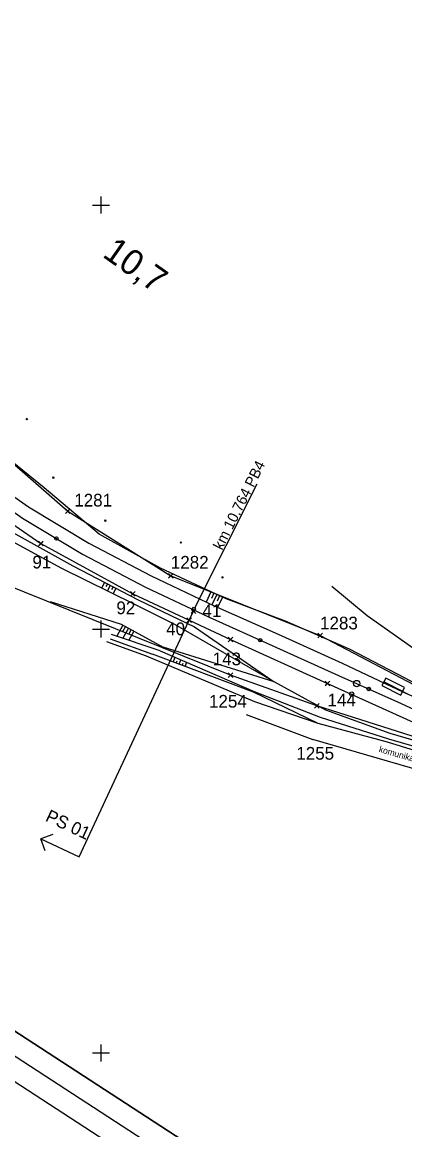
# Model space of a CAD drawing. Extents: x -866402 to -860377, y -1041908 to -1038598.
# Drawn here: x -861718.6 to -861628.2, y -1039718.2 to -1039456.8 of the extents above; entities that cross this region are included whole.
import ezdxf

# ---------------------------------------------------------------- set-up
doc = ezdxf.new("R2010")
doc.units = 0
for name, color, linetype in [('PS 01 prvky', 7, 'Continuous'), ('PS 01 trasa', 7, 'Continuous'), ('PS 02 trasa', 7, 'Continuous'), ('SZDC', 7, 'Continuous'), ('Vrstva 1', 7, 'Continuous'), ('Vrstva 17', 7, 'Continuous'), ('Vrstva 48', 7, 'Continuous'), ('Vrstva 49', 7, 'Continuous'), ('Vrstva 5', 7, 'Continuous'), ('Vrstva 51', 7, 'Continuous'), ('Vrstva 60', 7, 'Continuous'), ('Vrstva 7', 7, 'Continuous')]:
    doc.layers.add(name, color=color, linetype=linetype)

msp = doc.modelspace()

# ---------------------------------------------------------------- linework, layer by layer
at = {"layer": 'PS 01 prvky'}
for p, q in [((-861677.82, -1039594.99), (-861663.08, -1039565.75)), ((-861632.76, -1039611.58), (-861633.66, -1039613.36)), ((-861628.29, -1039613.81), (-861632.76, -1039611.58)), ((-861633.66, -1039613.36), (-861629.18, -1039615.6)), ((-861629.18, -1039615.6), (-861628.29, -1039613.81)), ((-861628.74, -1039614.71), (-861626.95, -1039615.6))]:
    msp.add_line(p, q, dxfattribs=at)
msp.add_lwpolyline([(-861677.61, -1039595.2), (-861678.29, -1039594.89), (-861678.6, -1039595.57), (-861677.92, -1039595.88)], close=True, dxfattribs=at)
for points in [[(-861678.11, -1039595.38), (-861678.45, -1039595.23)], [(-861628.74, -1039614.71), (-861633.21, -1039612.47)]]:
    msp.add_lwpolyline(points, dxfattribs=at)
at = {"layer": 'PS 01 trasa'}
for p, q in [((-861705.13, -1039653.71), (-861679.17, -1039597.93)), ((-861711.38, -1039648.46), (-861714.19, -1039649.49)), ((-861714.19, -1039649.49), (-861705.13, -1039653.71)), ((-861713.17, -1039652.31), (-861714.19, -1039649.49))]:
    msp.add_line(p, q, dxfattribs=at)
for points in [[(-861734.94, -1039565.48), (-861714.17, -1039579.85), (-861692.5, -1039591.72), (-861679.17, -1039597.93)], [(-861679.17, -1039597.93), (-861678.17, -1039595.76)]]:
    msp.add_lwpolyline(points, dxfattribs=at)
at = {"layer": 'PS 02 trasa'}
msp.add_lwpolyline([(-861734.94, -1039565.48), (-861714.17, -1039579.85), (-861692.5, -1039591.72), (-861679.17, -1039597.93), (-861669.42, -1039602.48), (-861646.49, -1039612.82), (-861623.81, -1039623.04), (-861599.73, -1039634.4), (-861591.94, -1039638.84), (-861559.23, -1039660.24), (-861540.24, -1039675.31), (-861522.22, -1039692.58), (-861505.35, -1039711.25), (-861489.08, -1039730.28), (-861472.81, -1039749.33), (-861456.55, -1039768.41), (-861440.35, -1039787.41)], dxfattribs=at)
at = {"layer": 'SZDC'}
for points in [[(-861729.85, -1039553), (-861707.85, -1039572.19), (-861683.49, -1039587.43), (-861648.26, -1039601.57), (-861584.91, -1039634.69), (-861543.49, -1039657.42), (-861534.95, -1039665.88), (-861527.09, -1039673.66), (-861519.15, -1039681.53), (-861498.94, -1039705.92), (-861489.43, -1039717.4), (-861392.94, -1039828.48), (-861296.45, -1039939.55), (-861273.55, -1039965.91), (-861261.75, -1039976.4), (-861207.66, -1040016.44)], [(-861236.71, -1040010.09), (-861295.08, -1039961.46), (-861327.14, -1039923.72), (-861355.62, -1039890.18), (-861362.07, -1039906.25), (-861375.91, -1039876.55), (-861379.94, -1039865.44), (-861377.18, -1039864.81), (-861381.07, -1039860.23), (-861505.7, -1039713.51), (-861552.61, -1039669.88), (-861558.17, -1039663.76), (-861561.3, -1039661.32), (-861593.45, -1039638.2), (-861610.89, -1039630.24), (-861649.01, -1039618.14), (-861669.39, -1039610.88), (-861739.98, -1039582.51)]]:
    msp.add_lwpolyline(points, dxfattribs=at)
at = {"layer": 'Vrstva 1'}
for points in [[(-862350.36, -1039297.02), (-861294.1, -1039983.97), (-861132.18, -1039735), (-862188.44, -1039048.05)], [(-862186.98, -1039054.97), (-861139.1, -1039736.46), (-861295.57, -1039977.05), (-862343.44, -1039295.55)], [(-862336.53, -1039294.09), (-861468.88, -1039858.37), (-861317.86, -1039626.16), (-862185.51, -1039061.88)], [(-862185.51, -1039061.88), (-861317.86, -1039626.16), (-861468.88, -1039858.37), (-862336.53, -1039294.09)]]:
    msp.add_lwpolyline(points, close=True, dxfattribs=at)
for points in [[(-861806.57, -1039466.19), (-861802.77, -1039473.87), (-861795.16, -1039488.58), (-861786.79, -1039503.21), (-861777.33, -1039517.47), (-861767.29, -1039530.41), (-861756.03, -1039542.96), (-861744.1, -1039554.37), (-861731.34, -1039564.81), (-861718.5, -1039573.84), (-861704.36, -1039582.33), (-861689.46, -1039590.11), (-861674.47, -1039597.17), (-861659.39, -1039604)], [(-861659.39, -1039604), (-861643.89, -1039610.95), (-861629.98, -1039617.19)], [(-861629.98, -1039617.19), (-861614.37, -1039624.37), (-861599.2, -1039631.91), (-861584.31, -1039640.17), (-861569.86, -1039649.29), (-861556.31, -1039658.9), (-861544.58, -1039668.2), (-861531.3, -1039680.04), (-861519.43, -1039691.88), (-861508.19, -1039704.07), (-861497.3, -1039716.49), (-861486.21, -1039729.46)]]:
    msp.add_lwpolyline(points, dxfattribs=at)
for centre in [(-861710.51, -1039578.64), (-861662.39, -1039602.64), (-861636.77, -1039614.15)]:
    msp.add_circle(centre, 0.4, dxfattribs=at)
at = {"layer": 'Vrstva 17'}
msp.add_lwpolyline([(-861593.79, -1039624.09), (-861605.28, -1039617.64), (-861620.25, -1039608.74), (-861637.16, -1039596.88), (-861645.51, -1039590.01)], dxfattribs=at)
at = {"layer": 'Vrstva 48'}
for p, q in [((-861699.13, -1039588.99), (-861699.84, -1039590.34)), ((-861698.46, -1039589.33), (-861698.81, -1039590.01)), ((-861697.8, -1039589.68), (-861698.49, -1039591.01)), ((-861697.13, -1039590.03), (-861697.48, -1039590.69)), ((-861696.47, -1039590.38), (-861697.15, -1039591.68)), ((-861674.03, -1039591.23), (-861675.17, -1039593.66)), ((-861673.35, -1039591.55), (-861673.92, -1039592.77)), ((-861672.67, -1039591.87), (-861673.82, -1039594.31)), ((-861671.99, -1039592.19), (-861672.56, -1039593.41)), ((-861671.31, -1039592.51), (-861672.45, -1039594.93)), ((-861694.84, -1039599.07), (-861696.28, -1039601.7)), ((-861694.19, -1039599.43), (-861694.87, -1039600.69)), ((-861693.53, -1039599.79), (-861694.84, -1039602.19)), ((-861692.87, -1039600.15), (-861693.49, -1039601.29)), ((-861692.21, -1039600.51), (-861693.39, -1039602.67)), ((-861682.91, -1039607.82), (-861682.48, -1039606.67)), ((-861682.21, -1039608.08), (-861682, -1039607.53)), ((-861681.51, -1039608.34), (-861681.1, -1039607.27)), ((-861680.81, -1039608.61), (-861680.61, -1039608.09)), ((-861680.1, -1039608.87), (-861679.73, -1039607.86))]:
    msp.add_line(p, q, dxfattribs=at)
at = {"layer": 'Vrstva 49'}
for p, q in [((-861717.68, -1039550.28), (-861717.33, -1039550.64)), ((-861717.68, -1039550.64), (-861717.33, -1039550.28)), ((-861711.42, -1039564.1), (-861711.06, -1039564.45)), ((-861711.42, -1039564.45), (-861711.06, -1039564.1)), ((-861699.15, -1039574.24), (-861698.8, -1039574.59)), ((-861699.15, -1039574.59), (-861698.8, -1039574.24)), ((-861681.33, -1039579.43), (-861680.97, -1039579.78)), ((-861681.33, -1039579.78), (-861680.97, -1039579.43)), ((-861671.47, -1039587.64), (-861671.11, -1039588)), ((-861671.47, -1039588), (-861671.11, -1039587.64)), ((-861697.81, -1039602.34), (-861687.84, -1039605.97)), ((-861686.05, -1039605.13), (-861697.51, -1039601.29)), ((-861663.99, -1039614.92), (-861687.84, -1039605.97)), ((-861631.69, -1039624.62), (-861646.9, -1039619.11))]:
    msp.add_line(p, q, dxfattribs=at)
for points in [[(-861800.02, -1039472.46), (-861791.33, -1039489.79), (-861784.32, -1039501.82), (-861775.23, -1039515.56), (-861765.55, -1039527.83), (-861753.79, -1039541.16), (-861742.23, -1039552.06), (-861729.5, -1039562.5), (-861717.12, -1039571.2), (-861702.84, -1039579.73), (-861688.14, -1039587.47), (-861673.27, -1039594.57), (-861658.14, -1039601.18), (-861643.02, -1039608.06), (-861628.53, -1039614.89), (-861613.05, -1039621.77), (-861598.1, -1039629.35)], [(-861597.49, -1039628.06), (-861608.55, -1039622.04), (-861628.17, -1039611.58), (-861641.27, -1039604.73), (-861656.44, -1039598.15), (-861670.44, -1039592.92), (-861685.95, -1039585.64), (-861700.43, -1039577.6), (-861713.44, -1039566.69), (-861724.4, -1039557.79), (-861736.43, -1039547.96), (-861748.45, -1039536.17), (-861760.78, -1039520.24), (-861769.59, -1039511.11), (-861778.23, -1039498.91)], [(-861720.79, -1039577.25), (-861706.62, -1039585.07), (-861691.24, -1039593.1), (-861677.89, -1039599.5), (-861659.07, -1039612.43)], [(-861659.07, -1039612.43), (-861682.56, -1039598.92), (-861692.14, -1039594.15), (-861709.22, -1039585.7), (-861720.83, -1039579.47)], [(-861711.97, -1039593.48), (-861695.23, -1039598.86), (-861685.28, -1039604.3)], [(-861686.05, -1039605.13), (-861663.79, -1039614.74), (-861648.21, -1039620.8)], [(-861646.9, -1039619.11), (-861659.07, -1039612.43), (-861685.28, -1039604.3)], [(-861600.49, -1039637.48), (-861616.86, -1039631.46), (-861632.31, -1039626.72), (-861648.71, -1039622.28), (-861663.99, -1039614.92)], [(-861648.21, -1039620.8), (-861632.07, -1039625.9), (-861616.55, -1039630.43)], [(-861600.85, -1039634.59), (-861616.02, -1039629.25), (-861631.69, -1039624.62)]]:
    msp.add_lwpolyline(points, dxfattribs=at)
at = {"layer": 'Vrstva 5'}
for p, q in [((-861700, -1039498), (-861700, -1039502)), ((-861702, -1039500), (-861698, -1039500)), ((-861702, -1039600), (-861698, -1039600)), ((-861700, -1039598), (-861700, -1039602)), ((-861700, -1039698), (-861700, -1039702)), ((-861702, -1039700), (-861698, -1039700))]:
    msp.add_line(p, q, dxfattribs=at)
at = {"layer": 'Vrstva 51'}
for p, q in [((-861648.71, -1039622.28), (-861663.69, -1039617.17)), ((-861665.68, -1039620.16), (-861649.97, -1039626.09))]:
    msp.add_line(p, q, dxfattribs=at)
for points in [[(-861663.69, -1039617.17), (-861689.27, -1039606.37), (-861698.57, -1039602.99)], [(-861600.49, -1039637.48), (-861616.86, -1039631.46), (-861632.31, -1039626.72), (-861648.71, -1039622.28)], [(-861601.57, -1039641.87), (-861611.67, -1039637.15), (-861649.97, -1039626.09)]]:
    msp.add_lwpolyline(points, dxfattribs=at)
at = {"layer": 'Vrstva 60'}
for p, q in [((-861707.4, -1039572.64), (-861708.4, -1039571.64)), ((-861707.4, -1039571.74), (-861708.4, -1039572.74)), ((-861708.3, -1039572.64), (-861707.3, -1039571.64)), ((-861708.3, -1039571.74), (-861707.3, -1039572.74)), ((-861707.85, -1039572.19), (-861707.85, -1039572.19)), ((-861713.72, -1039580.3), (-861714.72, -1039579.3)), ((-861714.62, -1039580.3), (-861713.62, -1039579.3)), ((-861713.72, -1039579.4), (-861714.72, -1039580.4)), ((-861714.62, -1039579.4), (-861713.62, -1039580.4)), ((-861714.17, -1039579.85), (-861714.17, -1039579.85)), ((-861683.04, -1039587.88), (-861684.04, -1039586.88)), ((-861683.04, -1039586.98), (-861684.04, -1039587.98)), ((-861683.94, -1039587.88), (-861682.94, -1039586.88)), ((-861683.94, -1039586.98), (-861682.94, -1039587.98)), ((-861683.49, -1039587.43), (-861683.49, -1039587.43)), ((-861692.05, -1039592.17), (-861693.05, -1039591.17)), ((-861692.05, -1039591.27), (-861693.05, -1039592.27)), ((-861692.95, -1039592.17), (-861691.95, -1039591.17)), ((-861692.95, -1039591.27), (-861691.95, -1039592.27)), ((-861692.5, -1039591.72), (-861692.5, -1039591.72)), ((-861678.72, -1039598.38), (-861679.72, -1039597.38)), ((-861678.72, -1039597.48), (-861679.72, -1039598.48)), ((-861679.62, -1039598.38), (-861678.62, -1039597.38)), ((-861679.62, -1039597.48), (-861678.62, -1039598.48)), ((-861677.72, -1039596.21), (-861678.72, -1039595.21)), ((-861677.72, -1039595.31), (-861678.72, -1039596.31)), ((-861678.62, -1039596.21), (-861677.62, -1039595.21)), ((-861678.62, -1039595.31), (-861677.62, -1039596.31)), ((-861678.17, -1039595.76), (-861678.17, -1039595.76)), ((-861679.17, -1039597.93), (-861679.17, -1039597.93)), ((-861668.97, -1039602.93), (-861669.97, -1039601.93)), ((-861668.97, -1039602.03), (-861669.97, -1039603.03)), ((-861669.87, -1039602.93), (-861668.87, -1039601.93)), ((-861669.87, -1039602.03), (-861668.87, -1039603.03)), ((-861669.42, -1039602.48), (-861669.42, -1039602.48)), ((-861647.81, -1039602.02), (-861648.81, -1039601.02)), ((-861647.81, -1039601.12), (-861648.81, -1039602.12)), ((-861648.71, -1039602.02), (-861647.71, -1039601.02)), ((-861648.71, -1039601.12), (-861647.71, -1039602.12)), ((-861648.26, -1039601.57), (-861648.26, -1039601.57)), ((-861668.94, -1039611.33), (-861669.94, -1039610.33)), ((-861668.94, -1039610.43), (-861669.94, -1039611.43)), ((-861669.84, -1039611.33), (-861668.84, -1039610.33)), ((-861669.84, -1039610.43), (-861668.84, -1039611.43)), ((-861669.39, -1039610.88), (-861669.39, -1039610.88)), ((-861646.04, -1039613.27), (-861647.04, -1039612.27)), ((-861646.04, -1039612.37), (-861647.04, -1039613.37)), ((-861646.94, -1039613.27), (-861645.94, -1039612.27)), ((-861646.94, -1039612.37), (-861645.94, -1039613.37)), ((-861646.49, -1039612.82), (-861646.49, -1039612.82)), ((-861648.56, -1039618.59), (-861649.56, -1039617.59)), ((-861648.56, -1039617.69), (-861649.56, -1039618.69)), ((-861649.46, -1039618.59), (-861648.46, -1039617.59)), ((-861649.46, -1039617.69), (-861648.46, -1039618.69)), ((-861649.01, -1039618.14), (-861649.01, -1039618.14))]:
    msp.add_line(p, q, dxfattribs=at)
at = {"layer": 'Vrstva 7'}
msp.add_line((-861640.83, -1039615.35), (-861640.73, -1039615.35), dxfattribs=at)
for centre, radius in [((-861639.6, -1039612.87), 0.75), ((-861640.78, -1039615.35), 0.5)]:
    msp.add_circle(centre, radius, dxfattribs=at)

# ---------------------------------------------------------------- texts
at = {"layer": 'PS 01 prvky'}
msp.add_text('km 10,764 PB4', height=2.5, rotation=63.2514, dxfattribs=at).set_placement((-861671.4, -1039581.54))
at = {"layer": 'PS 01 trasa'}
msp.add_text('PS 01', height=3, rotation=335.045, dxfattribs=at).set_placement((-861713.33, -1039645.19))
at = {"layer": 'Vrstva 51'}
msp.add_text('komunikace', height=1.5, rotation=343.903, dxfattribs=at).set_placement((-861634.48, -1039628.97))
at = {"layer": 'Vrstva 60'}
for s, p in [('1281', (-861706.3, -1039571.1)), ('91', (-861716.19, -1039585.72)), ('1282', (-861683.49, -1039585.76)), ('92', (-861696.35, -1039596.51)), ('41', (-861676.03, -1039597.18)), ('1283', (-861648.26, -1039600.09)), ('40', (-861684.6, -1039601.46)), ('143', (-861673.61, -1039608.55)), ('1254', (-861674.48, -1039618.55)), ('144', (-861646.49, -1039618.24)), ('1255', (-861653.86, -1039630.83))]:
    msp.add_text(s, height=3, dxfattribs=at).set_placement(p)
at = {"layer": 'Vrstva 7'}
msp.add_text('10,7', height=6, rotation=324.8952, dxfattribs=at).set_placement((-861699.88, -1039512.04))

doc.saveas('drawing.dxf')
